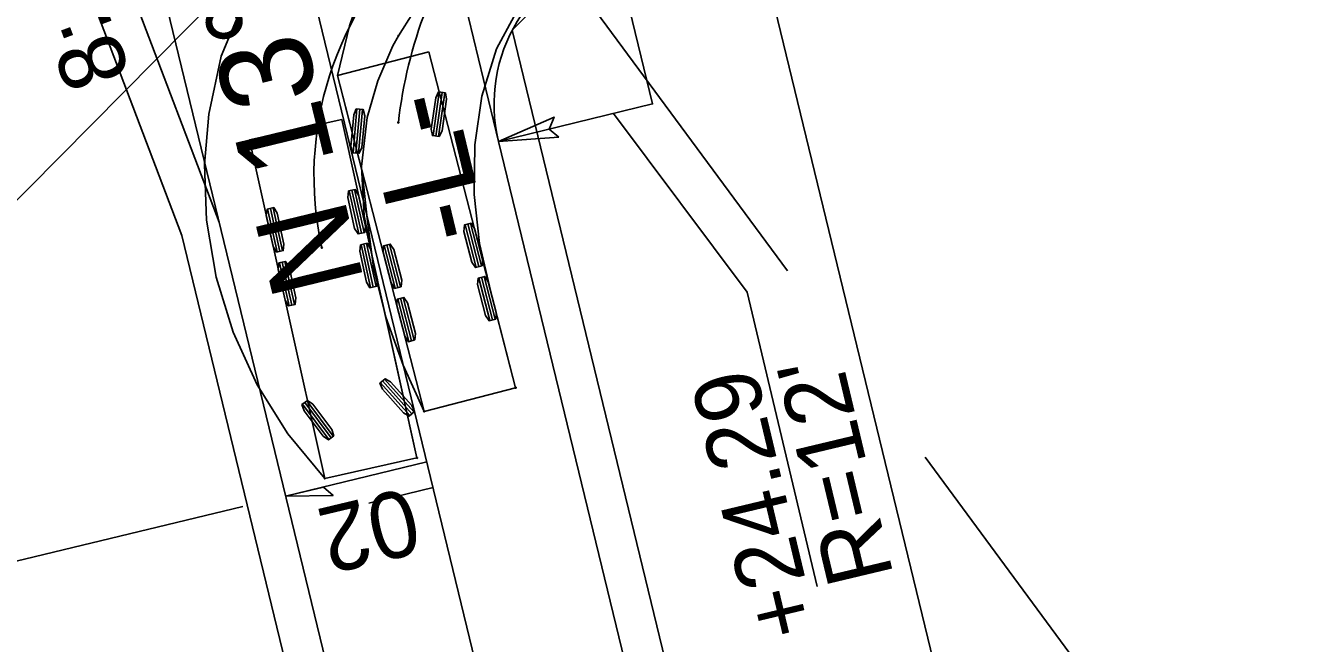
# Model space of a CAD drawing. Extents: x 1735795 to 1737428, y 699740 to 701024.
# Drawn here: x 1736230.5 to 1736328.4, y 700280.2 to 700327 of the extents above; entities that cross this region are included whole.
import ezdxf

# ---------------------------------------------------------------- set-up
doc = ezdxf.new("R2010")
doc.units = 0
for name, color, linetype in [('Prop Dimension', 7, 'Continuous'), ('Prop Dimension Text', 7, 'Continuous'), ('Prop EOT', 7, 'Continuous'), ('Prop Horizontal Alignment', 7, 'Continuous'), ('Prop Horizontal Alignment Direction Label', 7, 'Continuous'), ('Prop Horizontal Alignment Station Label', 7, 'Continuous'), ('Prop Horizontal Alignment Tick Small', 7, 'Continuous'), ('Prop Paved Shoulder', 7, 'Continuous'), ('Prop Superelevation  Arrow CELL', 7, 'Continuous'), ('Prop Terminator CELL', 7, 'Continuous'), ('Scratch_Level_2', 7, 'Continuous'), ('Scratch_Level_6', 7, 'Continuous'), ('Scratch_Level_7', 7, 'Continuous')]:
    doc.layers.add(name, color=color, linetype=linetype)

msp = doc.modelspace()

# ---------------------------------------------------------------- linework, layer by layer
at = {"layer": 'Prop Dimension'}
msp.add_line((1736246.968, 700290.597), (1736199.634, 700279.168), dxfattribs=at)
for points in [[(1736266.329, 700318.219), (1736277.99, 700321.051), (1736275.157, 700332.712)], [(1736275.037, 700320.334), (1736285.15, 700306.818), (1736290.455, 700284.547)]]:
    msp.add_lwpolyline(points, dxfattribs=at)
at = {"layer": 'Prop EOT'}
for p, q in [((1736261.304, 700245.692), (1736190.118, 700538.782)), ((1736256.888, 700357.089), (1736266.329, 700318.219)), ((1736282.683, 700250.885), (1736266.329, 700318.219))]:
    msp.add_line(p, q, dxfattribs=at)
msp.add_arc((1736277.99, 700321.051), 12, 103.65186, 193.65186, dxfattribs=at)
at = {"layer": 'Prop Horizontal Alignment'}
msp.add_line((1736284.975, 700194.842), (1736200.807, 700541.379), dxfattribs=at)
at = {"layer": 'Prop Horizontal Alignment Station Label'}
for p, q in [((1736284.038, 700341.558), (1736327.269, 700163.564)), ((1736288.213, 700308.426), (1736265.869, 700338.689)), ((1736250.919, 700335.057), (1736104.013, 700186.731)), ((1736328.388, 700254.014), (1736298.631, 700294.316))]:
    msp.add_line(p, q, dxfattribs=at)
at = {"layer": 'Prop Horizontal Alignment Tick Small'}
msp.add_line((1736261.373, 700292.017), (1736256.514, 700290.837), dxfattribs=at)
at = {"layer": 'Prop Paved Shoulder'}
msp.add_line((1736245.174, 700312.106), (1736229.723, 700352.809), dxfattribs=at)
at = {"layer": 'Prop Superelevation  Arrow CELL'}
msp.add_line((1736260.901, 700293.961), (1736250.208, 700291.379), dxfattribs=at)
msp.add_lwpolyline([(1736250.208, 700291.379), (1736253.798, 700291.412), (1736253.077, 700292.063)], close=True, dxfattribs=at)
at = {"layer": 'Prop Terminator CELL'}
msp.add_lwpolyline([(1736270.884, 700318.528), (1736266.329, 700318.219), (1736270.537, 700320.064), (1736270.167, 700319.151)], close=True, dxfattribs=at)
at = {"layer": 'Scratch_Level_2'}
for p, q in [((1736242.334, 700311.086), (1736226.832, 700351.945)), ((1736267.37, 700326.64), (1736271.854, 700331.131)), ((1736285.615, 700251.525), (1736267.37, 700326.64)), ((1736258.407, 700244.912), (1736242.334, 700311.086))]:
    msp.add_line(p, q, dxfattribs=at)
at = {"layer": 'Scratch_Level_6'}
for p, q in [((1736261.056, 700324.991), (1736254.131, 700323.201)), ((1736267.622, 700299.579), (1736261.056, 700324.991)), ((1736254.131, 700323.201), (1736260.697, 700297.789)), ((1736254.131, 700323.201), (1736254.131, 700323.201)), ((1736261.842, 700321.955), (1736261.366, 700318.656)), ((1736262.049, 700321.925), (1736261.572, 700318.626)), ((1736262.255, 700321.895), (1736261.778, 700318.596)), ((1736255.609, 700320.677), (1736255.319, 700317.357)), ((1736255.816, 700320.659), (1736255.527, 700317.339)), ((1736256.024, 700320.641), (1736255.734, 700317.321)), ((1736264.622, 700308.688), (1736263.789, 700311.916)), ((1736264.824, 700308.74), (1736263.99, 700311.968)), ((1736265.026, 700308.792), (1736264.192, 700312.02)), ((1736258.505, 700307.107), (1736257.671, 700310.335)), ((1736258.706, 700307.16), (1736257.872, 700310.387)), ((1736258.908, 700307.212), (1736258.074, 700310.439)), ((1736265.665, 700304.654), (1736264.831, 700307.881)), ((1736265.867, 700304.706), (1736265.033, 700307.933)), ((1736266.068, 700304.758), (1736265.234, 700307.986)), ((1736259.547, 700303.073), (1736258.713, 700306.301)), ((1736259.749, 700303.125), (1736258.915, 700306.353)), ((1736259.95, 700303.177), (1736259.116, 700306.405)), ((1736260.697, 700297.789), (1736267.622, 700299.579))]:
    msp.add_line(p, q, dxfattribs=at)
for points in [[(1736260.697, 700297.789), (1736259.1, 700301.289), (1736257.784, 700304.922), (1736256.847, 700308.666), (1736256.368, 700312.38), (1736256.007, 700315.941), (1736255.069, 700319.571), (1736254.131, 700323.201), (1736254.131, 700323.201), (1736255.038, 700326.972), (1736256.307, 700330.638), (1736257.926, 700334.165), (1736259.88, 700337.519), (1736260.309, 700338.167)], [(1736267.622, 700299.579), (1736266.684, 700303.209), (1736265.746, 700306.839), (1736264.892, 700310.489), (1736264.472, 700314.209), (1736264.53, 700317.951), (1736265.067, 700321.652), (1736266.161, 700325.22), (1736266.161, 700325.22), (1736266.161, 700325.22), (1736267.509, 700327.691), (1736269.275, 700329.877), (1736271.338, 700331.784), (1736273.601, 700333.447), (1736274.075, 700333.748)]]:
    msp.add_lwpolyline(points, dxfattribs=at)
for points in [[(1736261.791, 700321.962), (1736262.306, 700321.888), (1736262.394, 700321.404), (1736262.051, 700319.028), (1736261.829, 700318.589), (1736261.315, 700318.663), (1736261.226, 700319.147), (1736261.569, 700321.523)], [(1736255.557, 700320.682), (1736256.075, 700320.637), (1736256.191, 700320.158), (1736255.983, 700317.767), (1736255.786, 700317.316), (1736255.268, 700317.361), (1736255.152, 700317.84), (1736255.361, 700320.231)], [(1736265.076, 700308.805), (1736264.572, 700308.675), (1736264.304, 700309.088), (1736263.704, 700311.412), (1736263.739, 700311.903), (1736264.242, 700312.033), (1736264.51, 700311.62), (1736265.111, 700309.296)], [(1736258.958, 700307.225), (1736258.455, 700307.094), (1736258.186, 700307.507), (1736257.586, 700309.831), (1736257.621, 700310.322), (1736258.124, 700310.452), (1736258.393, 700310.039), (1736258.993, 700307.716)], [(1736266.118, 700304.771), (1736265.615, 700304.641), (1736265.346, 700305.054), (1736264.746, 700307.377), (1736264.781, 700307.868), (1736265.284, 700307.999), (1736265.553, 700307.586), (1736266.153, 700305.262)], [(1736260, 700303.19), (1736259.497, 700303.06), (1736259.228, 700303.473), (1736258.628, 700305.797), (1736258.663, 700306.288), (1736259.166, 700306.418), (1736259.435, 700306.005), (1736260.035, 700303.681)]]:
    msp.add_lwpolyline(points, close=True, dxfattribs=at)
for centre in [(1736258.742, 700319.649), (1736267.622, 700299.579), (1736260.697, 700297.789)]:
    msp.add_circle(centre, 0.0417, dxfattribs=at)
msp.add_arc((1736293.447, 700315.706), 34.928, 144.5971, 173.51766, dxfattribs=at)
at = {"layer": 'Scratch_Level_7'}
for p, q in [((1736254.45, 700319.886), (1736247.468, 700318.333)), ((1736260.15, 700294.266), (1736254.45, 700319.886)), ((1736247.468, 700318.333), (1736253.169, 700292.713)), ((1736255.013, 700314.476), (1736255.737, 700311.222)), ((1736255.217, 700314.521), (1736255.941, 700311.268)), ((1736255.42, 700314.567), (1736256.144, 700311.313)), ((1736248.845, 700313.104), (1736249.569, 700309.85)), ((1736249.049, 700313.149), (1736249.773, 700309.895)), ((1736249.252, 700313.194), (1736249.976, 700309.94)), ((1736255.918, 700310.409), (1736256.642, 700307.155)), ((1736256.122, 700310.454), (1736256.846, 700307.2)), ((1736256.325, 700310.499), (1736257.049, 700307.246)), ((1736249.75, 700309.036), (1736250.474, 700305.783)), ((1736249.954, 700309.082), (1736250.678, 700305.828)), ((1736250.157, 700309.127), (1736250.881, 700305.873)), ((1736259.607, 700297.467), (1736257.381, 700299.948)), ((1736259.762, 700297.606), (1736257.537, 700300.088)), ((1736259.917, 700297.745), (1736257.692, 700300.227)), ((1736253.65, 700295.793), (1736251.652, 700298.462)), ((1736253.817, 700295.918), (1736251.819, 700298.587)), ((1736253.483, 700295.669), (1736251.485, 700298.337)), ((1736253.169, 700292.713), (1736260.15, 700294.266)), ((1736260.15, 700294.266), (1736260.15, 700294.266))]:
    msp.add_line(p, q, dxfattribs=at)
for points in [[(1736258.746, 700326.215), (1736259.832, 700327.922), (1736261.653, 700330.167), (1736263.756, 700332.151), (1736266.069, 700333.886), (1736268.555, 700335.366)], [(1736253.169, 700292.713), (1736253.169, 700292.713), (1736250.371, 700296.086), (1736248.042, 700299.795), (1736246.222, 700303.773), (1736244.94, 700307.952), (1736244.218, 700312.254), (1736244.061, 700316.472), (1736244.38, 700320.277), (1736244.38, 700320.277), (1736245.312, 700324.675), (1736247, 700328.66), (1736247.603, 700329.802)], [(1736260.15, 700294.266), (1736259.336, 700297.926), (1736258.522, 700301.586), (1736257.707, 700305.246), (1736256.893, 700308.906), (1736256.141, 700312.578), (1736255.939, 700316.313), (1736256.389, 700320.022), (1736256.389, 700320.022), (1736257.176, 700322.803), (1736258.331, 700325.453), (1736258.746, 700326.215)]]:
    msp.add_lwpolyline(points, dxfattribs=at)
for points in [[(1736254.963, 700314.465), (1736255.471, 700314.578), (1736255.725, 700314.156), (1736256.246, 700311.814), (1736256.194, 700311.324), (1736255.687, 700311.211), (1736255.433, 700311.633), (1736254.911, 700313.975)], [(1736248.795, 700313.092), (1736249.302, 700313.205), (1736249.557, 700312.784), (1736250.078, 700310.441), (1736250.026, 700309.952), (1736249.519, 700309.839), (1736249.265, 700310.26), (1736248.743, 700312.603)], [(1736255.868, 700310.398), (1736256.375, 700310.511), (1736256.63, 700310.089), (1736257.151, 700307.746), (1736257.099, 700307.257), (1736256.592, 700307.144), (1736256.338, 700307.565), (1736255.816, 700309.908)], [(1736249.7, 700309.025), (1736250.207, 700309.138), (1736250.462, 700308.717), (1736250.983, 700306.374), (1736250.931, 700305.884), (1736250.424, 700305.771), (1736250.169, 700306.193), (1736249.648, 700308.536)], [(1736259.956, 700297.78), (1736259.569, 700297.433), (1736259.141, 700297.675), (1736257.538, 700299.462), (1736257.343, 700299.914), (1736257.73, 700300.261), (1736258.158, 700300.018), (1736259.761, 700298.232)], [(1736253.858, 700295.949), (1736253.442, 700295.638), (1736253.037, 700295.917), (1736251.598, 700297.838), (1736251.444, 700298.306), (1736251.86, 700298.618), (1736252.265, 700298.338), (1736253.704, 700296.417)]]:
    msp.add_lwpolyline(points, close=True, dxfattribs=at)
for centre in [(1736258.746, 700326.215), (1736258.746, 700326.215), (1736252.947, 700310.175), (1736260.15, 700294.266), (1736253.169, 700292.713)]:
    msp.add_circle(centre, 0.0417, dxfattribs=at)
msp.add_arc((1736277.324, 700315.598), 24.973, 132.12967, 192.5438, dxfattribs=at)

# ---------------------------------------------------------------- texts
at = {"layer": 'Prop Dimension Text'}
for s, rotation, p in [('8:1', 110.41421, (1736238.53, 700323.299)), ('+24.29', 103.41838, (1736290.502, 700281.236)), ("R=12'", 103.41838, (1736296.256, 700285.364))]:
    msp.add_text(s, height=5, rotation=rotation, dxfattribs=at).set_placement(p)
at = {"layer": 'Prop Horizontal Alignment Direction Label'}
for s, rotation, p in [('N 13%%d 39\' 06.7" W', 103.65186, (1736256.186, 700307.582)), ('-L-', 103.50501, (1736265.515, 700311.337))]:
    msp.add_text(s, height=7, rotation=rotation, dxfattribs=at).set_placement(p)
at = {"layer": 'Prop Superelevation  Arrow CELL'}
msp.add_text('02', height=5, rotation=193.41029, dxfattribs=at).set_placement((1736259.594, 700292.054))

doc.saveas('drawing.dxf')
